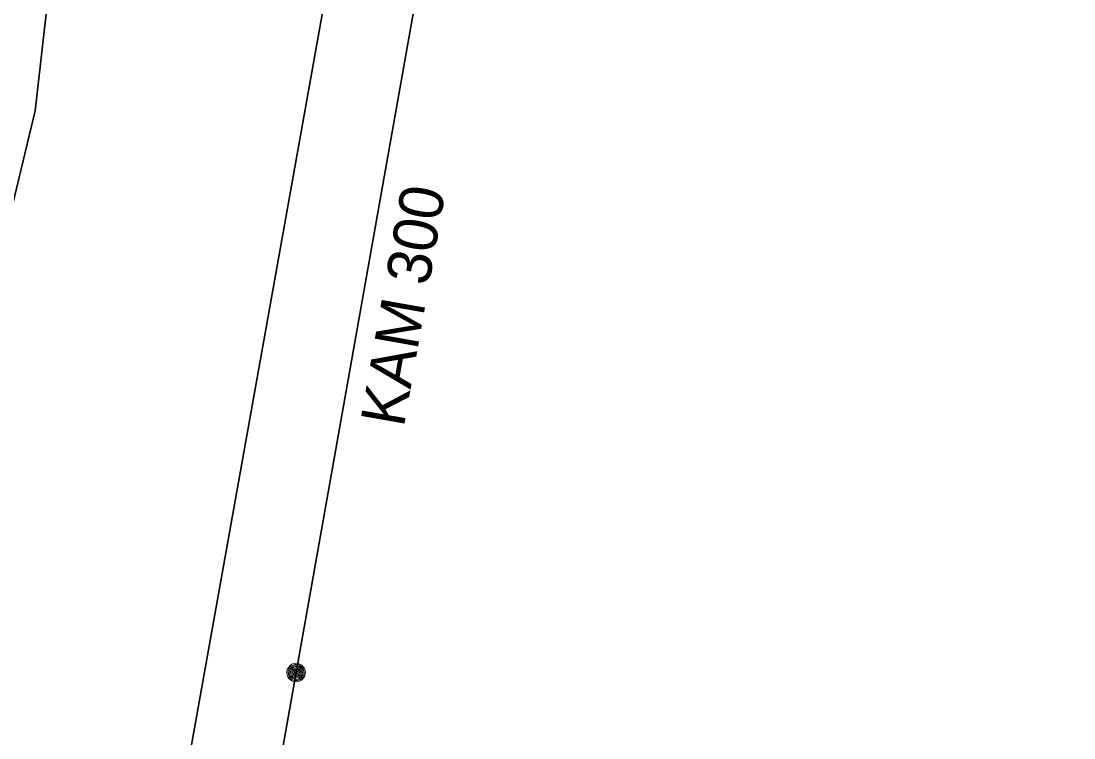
# Model space of a CAD drawing. Extents: x -867121 to -866743, y -1014362 to -1014088.
# Drawn here: x -866794.67 to -866768.34, y -1014243.81 to -1014225.88 of the extents above; entities that cross this region are included whole.
import ezdxf

# ---------------------------------------------------------------- set-up
doc = ezdxf.new("R2010")
doc.units = 0
doc.header["$LTSCALE"] = 0.44
for name, color, linetype, lineweight in [('1', 7, 'Continuous', 35), ('21', 7, 'Continuous', 35), ('32', 7, 'Continuous', 13)]:
    doc.layers.add(name, color=color, linetype=linetype, lineweight=lineweight)

msp = doc.modelspace()

# ---------------------------------------------------------------- linework, layer by layer
at = {"layer": '1'}
msp.add_lwpolyline([(-866791.979, -1014256.58), (-866792.57, -1014256.02), (-866792.709, -1014255.69), (-866792.69, -1014255.37), (-866792.5, -1014254.9), (-866792.3, -1014254.24), (-866792, -1014252.89), (-866783.03, -1014202.67), (-866778.1, -1014171.95), (-866772.02, -1014133.72), (-866768.851, -1014115.7)], dxfattribs=at)
at = {"layer": '21'}
for p, q in [((-866787.796, -1014242.174), (-866783.712, -1014219.159)), ((-866789.484, -1014251.689), (-866787.796, -1014242.174))]:
    msp.add_line(p, q, dxfattribs=at)
msp.add_lwpolyline([(-866867.906, -1014313.414), (-866804.195, -1014269.207), (-866794.318, -1014228.125), (-866791.378, -1014202.173), (-866784.04, -1014170.77), (-866768.345, -1014133.735)], dxfattribs=at)
at = {"layer": '32'}
for points in [[(-866787.565, -1014242.174), (-866787.571, -1014242.122), (-866787.588, -1014242.072), (-866787.617, -1014242.028), (-866787.654, -1014241.991), (-866787.699, -1014241.964), (-866787.749, -1014241.947), (-866787.802, -1014241.943), (-866787.853, -1014241.95), (-866787.902, -1014241.969), (-866787.946, -1014241.998), (-866787.982, -1014242.037), (-866788.008, -1014242.082), (-866788.024, -1014242.133), (-866788.027, -1014242.185), (-866788.019, -1014242.237), (-866787.999, -1014242.286), (-866787.968, -1014242.329), (-866787.929, -1014242.363), (-866787.883, -1014242.389), (-866787.831, -1014242.403), (-866787.779, -1014242.405), (-866787.728, -1014242.395), (-866787.679, -1014242.374), (-866787.637, -1014242.343), (-866787.603, -1014242.302), (-866787.579, -1014242.256), (-866787.566, -1014242.205)], [(-866787.595, -1014242.174), (-866787.601, -1014242.125), (-866787.618, -1014242.079), (-866787.646, -1014242.039), (-866787.683, -1014242.007), (-866787.727, -1014241.985), (-866787.775, -1014241.974), (-866787.824, -1014241.974), (-866787.87, -1014241.987), (-866787.914, -1014242.011), (-866787.95, -1014242.044), (-866787.977, -1014242.085), (-866787.993, -1014242.132), (-866787.997, -1014242.181), (-866787.99, -1014242.229), (-866787.971, -1014242.274), (-866787.941, -1014242.314), (-866787.902, -1014242.345), (-866787.858, -1014242.365), (-866787.811, -1014242.375), (-866787.762, -1014242.373), (-866787.715, -1014242.358), (-866787.672, -1014242.333), (-866787.637, -1014242.299), (-866787.612, -1014242.257), (-866787.598, -1014242.21)], [(-866787.625, -1014242.174), (-866787.63, -1014242.129), (-866787.647, -1014242.087), (-866787.676, -1014242.052), (-866787.712, -1014242.025), (-866787.754, -1014242.008), (-866787.799, -1014242.003), (-866787.843, -1014242.009), (-866787.885, -1014242.028), (-866787.919, -1014242.056), (-866787.946, -1014242.093), (-866787.963, -1014242.135), (-866787.967, -1014242.18), (-866787.96, -1014242.225), (-866787.941, -1014242.266), (-866787.912, -1014242.3), (-866787.875, -1014242.326), (-866787.831, -1014242.342), (-866787.787, -1014242.345), (-866787.742, -1014242.337), (-866787.701, -1014242.317), (-866787.668, -1014242.288), (-866787.642, -1014242.25), (-866787.628, -1014242.207)], [(-866787.655, -1014242.174), (-866787.659, -1014242.133), (-866787.678, -1014242.096), (-866787.705, -1014242.065), (-866787.74, -1014242.044), (-866787.78, -1014242.033), (-866787.821, -1014242.035), (-866787.86, -1014242.048), (-866787.894, -1014242.072), (-866787.919, -1014242.104), (-866787.934, -1014242.142), (-866787.936, -1014242.183), (-866787.929, -1014242.223), (-866787.909, -1014242.259), (-866787.88, -1014242.288), (-866787.843, -1014242.307), (-866787.803, -1014242.315), (-866787.762, -1014242.311), (-866787.723, -1014242.296), (-866787.691, -1014242.27), (-866787.669, -1014242.236), (-866787.656, -1014242.197)], [(-866787.684, -1014242.174), (-866787.69, -1014242.138), (-866787.708, -1014242.106), (-866787.733, -1014242.081), (-866787.767, -1014242.066), (-866787.804, -1014242.063), (-866787.838, -1014242.071), (-866787.87, -1014242.091), (-866787.892, -1014242.119), (-866787.906, -1014242.153), (-866787.906, -1014242.19), (-866787.895, -1014242.225), (-866787.874, -1014242.254), (-866787.843, -1014242.275), (-866787.809, -1014242.285), (-866787.772, -1014242.283), (-866787.738, -1014242.269), (-866787.711, -1014242.246), (-866787.691, -1014242.214), (-866787.684, -1014242.179)], [(-866787.715, -1014242.174), (-866787.72, -1014242.143), (-866787.737, -1014242.117), (-866787.762, -1014242.1), (-866787.793, -1014242.093), (-866787.824, -1014242.097), (-866787.851, -1014242.114), (-866787.869, -1014242.138), (-866787.877, -1014242.169), (-866787.873, -1014242.199), (-866787.858, -1014242.227), (-866787.833, -1014242.246), (-866787.804, -1014242.255), (-866787.772, -1014242.252), (-866787.745, -1014242.238), (-866787.725, -1014242.214), (-866787.715, -1014242.185)], [(-866787.745, -1014242.174), (-866787.75, -1014242.15), (-866787.767, -1014242.132), (-866787.789, -1014242.123), (-866787.814, -1014242.126), (-866787.835, -1014242.14), (-866787.846, -1014242.162), (-866787.846, -1014242.187), (-866787.833, -1014242.208), (-866787.814, -1014242.222), (-866787.789, -1014242.225), (-866787.766, -1014242.216), (-866787.75, -1014242.198)], [(-866787.775, -1014242.174), (-866787.78, -1014242.159), (-866787.794, -1014242.153), (-866787.809, -1014242.157), (-866787.816, -1014242.171), (-866787.813, -1014242.186), (-866787.799, -1014242.195), (-866787.784, -1014242.192), (-866787.775, -1014242.18)]]:
    msp.add_lwpolyline(points, close=True, dxfattribs=at)

# ---------------------------------------------------------------- texts
at = {"layer": '1'}
msp.add_text('KAM 300 ', height=1.1, rotation=80, dxfattribs=at).set_placement((-866785.106, -1014236.064))

doc.saveas('drawing.dxf')
